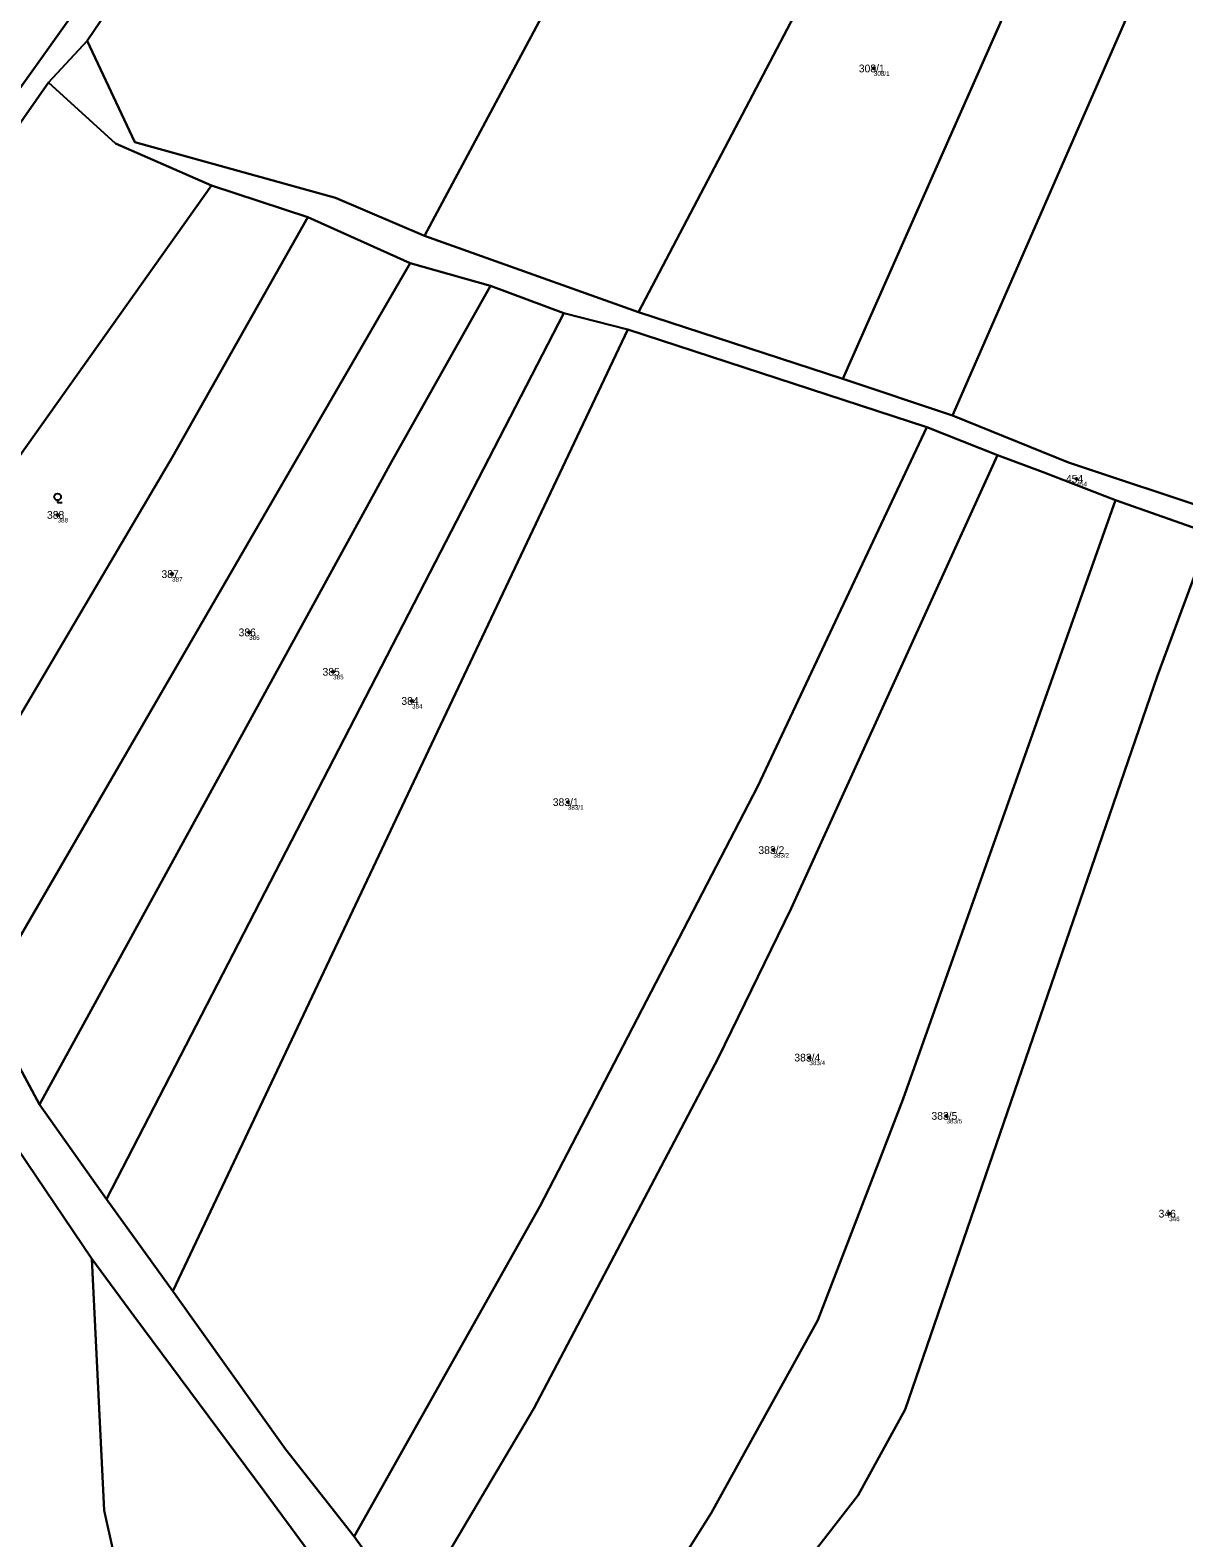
# Model space of a CAD drawing. Extents: x -700238 to -698499, y -1070626 to -1068006.
# Drawn here: x -699749.9 to -699496.8, y -1070051.8 to -1069721.2 of the extents above; entities that cross this region are included whole.
import ezdxf

# ---------------------------------------------------------------- set-up
doc = ezdxf.new("R2010")
doc.units = 0
for name, color, linetype in [('Definiční body', 7, 'Continuous'), ('Hranice parcel', 7, 'Continuous'), ('Parcelní čísla', 7, 'Continuous'), ('Polygon parcely', 7, 'Continuous'), ('Značky kultur', 7, 'Continuous')]:
    doc.layers.add(name, color=color, linetype=linetype)

msp = doc.modelspace()

# ---------------------------------------------------------------- linework, layer by layer
at = {"layer": 'Definiční body'}
for centre in [(-699564.79, -1069729.56994), (-699520.33, -1069819.56994), (-699743.85, -1069827.47994), (-699718.73, -1069840.45994), (-699701.82, -1069853.23994), (-699683.4, -1069861.88994), (-699666.11, -1069868.27994), (-699631.92, -1069890.46994), (-699586.82, -1069900.98994), (-699578.93, -1069946.48994), (-699548.86, -1069959.26994), (-699500, -1069980.70994)]:
    msp.add_circle(centre, 0.25, dxfattribs=at)
at = {"layer": 'Hranice parcel'}
for p, q in [((-699616.44, -1069783.03), (-699549.64, -1069655.89)), ((-699571.62, -1069797.63), (-699516.58, -1069673.38)), ((-699737.33, -1069723.55), (-699745.82, -1069732.62)), ((-699745.82, -1069732.62), (-699776.22, -1069775.97)), ((-699710.07, -1069755.22), (-699786.04, -1069862.19)), ((-699688.94, -1069762.18), (-699710.07, -1069755.22)), ((-699688.94, -1069762.18), (-699666.52, -1069772.25)), ((-699616.44, -1069783.03), (-699663.38, -1069766.26)), ((-699666.52, -1069772.25), (-699760.19, -1069933.83)), ((-699666.52, -1069772.25), (-699648.85, -1069777.23)), ((-699648.85, -1069777.23), (-699632.79, -1069783.26)), ((-699571.62, -1069797.63), (-699616.44, -1069783.03)), ((-699632.79, -1069783.26), (-699618.77, -1069786.84)), ((-699618.77, -1069786.84), (-699553.13, -1069808.24)), ((-699547.54, -1069805.7), (-699571.62, -1069797.63)), ((-699553.13, -1069808.24), (-699537.64, -1069814.41)), ((-699511.76, -1069824.23), (-699491.01, -1069831.53)), ((-699747.8, -1069956.79), (-699760.19, -1069933.83)), ((-699733.13, -1069977.54), (-699747.8, -1069956.79)), ((-699718.55, -1069997.74), (-699733.13, -1069977.54)), ((-699666.31, -1070068.88), (-699678.79, -1070051.48))]:
    msp.add_line(p, q, dxfattribs=at)
for points in [[(-699663.38, -1069766.26), (-699588.64, -1069626.6), (-699502.63, -1069463.58)], [(-699410.28, -1069497.79), (-699441.48, -1069563.72), (-699499.48, -1069695.89), (-699547.54, -1069805.7)], [(-699737.33, -1069723.55), (-699717.02, -1069693.47), (-699659.11, -1069627.7), (-699618.38, -1069587.63), (-699595.53, -1069569.04), (-699577.69, -1069541.99)], [(-699807.41, -1069785.71), (-699794.66, -1069783.16), (-699779.48, -1069772.23), (-699717.6, -1069685.48), (-699696.09, -1069660.07), (-699677.27, -1069640.4)], [(-699663.38, -1069766.26), (-699682.85, -1069757.92), (-699726.9, -1069745.77), (-699737.33, -1069723.55)], [(-699710.07, -1069755.22), (-699731.13, -1069746.06), (-699745.82, -1069732.62)], [(-699772.32, -1069905.7), (-699718.65, -1069814.76), (-699688.94, -1069762.18)], [(-699648.85, -1069777.23), (-699670.62, -1069815.86), (-699747.8, -1069956.79)], [(-699632.79, -1069783.26), (-699678.65, -1069872.05), (-699733.13, -1069977.54)], [(-699618.77, -1069786.84), (-699666.98, -1069888.75), (-699718.55, -1069997.74)], [(-699489.13, -1069826.97), (-699522.09, -1069816), (-699547.54, -1069805.7)], [(-699678.79, -1070051.48), (-699638.09, -1069979.15), (-699590.2, -1069886.97), (-699553.13, -1069808.24)], [(-699666.31, -1070068.88), (-699639.37, -1070023.43), (-699598.96, -1069946.58), (-699582.95, -1069913.77), (-699537.64, -1069814.41)], [(-699537.64, -1069814.41), (-699527.68, -1069818.13), (-699511.76, -1069824.23)], [(-699638.4, -1070106.69), (-699600.44, -1070046.39), (-699577.04, -1070004.06), (-699558.35, -1069955.5), (-699511.76, -1069824.23)], [(-699491.01, -1069831.53), (-699502.67, -1069862.92), (-699557.9, -1070023.63), (-699568.2, -1070042.42), (-699591.03, -1070071.83), (-699598.11, -1070087.48), (-699605.82, -1070099.55), (-699627.96, -1070121.02)], [(-699773.88, -1069925.87), (-699754.67, -1069963.44), (-699736.31, -1069990.62)], [(-699719.44, -1070141.14), (-699723.72, -1070090.01), (-699733.66, -1070045.81), (-699736.31, -1069990.62)], [(-699736.31, -1069990.62), (-699727.1, -1070003.14), (-699698.54, -1070041.6), (-699662.16, -1070090.9)], [(-699678.79, -1070051.48), (-699693.87, -1070032.39), (-699718.55, -1069997.74)]]:
    msp.add_lwpolyline(points, dxfattribs=at)
at = {"layer": 'Polygon parcely'}
for points in [[(-699588.64, -1069626.6), (-699502.63, -1069463.58), (-699532.43, -1069462.36), (-699542.13, -1069479.46), (-699556.41, -1069509.75), (-699574.72, -1069544.15), (-699577.69, -1069541.99), (-699595.53, -1069569.04), (-699618.38, -1069587.63), (-699659.11, -1069627.7), (-699717.02, -1069693.47), (-699737.33, -1069723.55), (-699726.9, -1069745.77), (-699682.85, -1069757.92), (-699663.38, -1069766.26)], [(-699549.64, -1069655.89), (-699502.55, -1069565.81), (-699455.2, -1069475.22), (-699473.03, -1069469.4), (-699502.63, -1069463.58), (-699588.64, -1069626.6), (-699663.38, -1069766.26), (-699616.44, -1069783.03)], [(-699432.05, -1069485.06), (-699452.42, -1069528.96), (-699490.02, -1069614.95), (-699516.58, -1069673.38), (-699571.62, -1069797.63), (-699547.54, -1069805.7), (-699499.48, -1069695.89), (-699441.48, -1069563.72), (-699410.28, -1069497.79), (-699430.38, -1069485.94)], [(-699441.48, -1069563.72), (-699499.48, -1069695.89), (-699547.54, -1069805.7), (-699522.09, -1069816), (-699489.13, -1069826.97), (-699429.43, -1069642.62), (-699387.77, -1069511.65), (-699407.42, -1069499.79), (-699410.28, -1069497.79)], [(-699794.66, -1069783.16), (-699779.48, -1069772.23), (-699717.6, -1069685.48), (-699696.09, -1069660.07), (-699677.27, -1069640.4), (-699685.96, -1069634.32), (-699687.82, -1069636.88), (-699698.97, -1069628.88), (-699715.89, -1069617.34), (-699724.79, -1069614.07), (-699727.16, -1069611.21), (-699737.97, -1069630.27), (-699758.73, -1069669.77), (-699796.03, -1069732.47), (-699807.3, -1069760.27), (-699807.41, -1069785.71)], [(-699516.58, -1069673.38), (-699549.64, -1069655.89), (-699616.44, -1069783.03), (-699571.62, -1069797.63)], [(-699745.82, -1069732.62), (-699776.22, -1069775.97), (-699788.87, -1069798.41), (-699791.36, -1069813.75), (-699786.04, -1069862.19), (-699710.07, -1069755.22), (-699731.13, -1069746.06)], [(-699718.65, -1069814.76), (-699688.94, -1069762.18), (-699710.07, -1069755.22), (-699786.04, -1069862.19), (-699772.32, -1069905.7)], [(-699772.32, -1069905.7), (-699760.19, -1069933.83), (-699666.52, -1069772.25), (-699688.94, -1069762.18), (-699718.65, -1069814.76)], [(-699666.52, -1069772.25), (-699760.19, -1069933.83), (-699747.8, -1069956.79), (-699670.62, -1069815.86), (-699648.85, -1069777.23)], [(-699648.85, -1069777.23), (-699670.62, -1069815.86), (-699747.8, -1069956.79), (-699733.13, -1069977.54), (-699678.65, -1069872.05), (-699632.79, -1069783.26)], [(-699678.65, -1069872.05), (-699733.13, -1069977.54), (-699718.55, -1069997.74), (-699666.98, -1069888.75), (-699618.77, -1069786.84), (-699632.79, -1069783.26)], [(-699638.09, -1069979.15), (-699590.2, -1069886.97), (-699553.13, -1069808.24), (-699618.77, -1069786.84), (-699666.98, -1069888.75), (-699718.55, -1069997.74), (-699693.87, -1070032.39), (-699678.79, -1070051.48)], [(-699639.37, -1070023.43), (-699598.96, -1069946.58), (-699582.95, -1069913.77), (-699537.64, -1069814.41), (-699553.13, -1069808.24), (-699590.2, -1069886.97), (-699638.09, -1069979.15), (-699678.79, -1070051.48), (-699666.31, -1070068.88)], [(-699511.76, -1069824.23), (-699527.68, -1069818.13), (-699537.64, -1069814.41), (-699582.95, -1069913.77), (-699598.96, -1069946.58), (-699639.37, -1070023.43), (-699666.31, -1070068.88), (-699659.02, -1070078.07), (-699638.4, -1070106.69), (-699600.44, -1070046.39), (-699577.04, -1070004.06), (-699558.35, -1069955.5)], [(-699627.96, -1070121.02), (-699605.82, -1070099.55), (-699598.11, -1070087.48), (-699591.03, -1070071.83), (-699568.2, -1070042.42), (-699557.9, -1070023.63), (-699502.67, -1069862.92), (-699491.01, -1069831.53), (-699511.76, -1069824.23), (-699558.35, -1069955.5), (-699577.04, -1070004.06), (-699600.44, -1070046.39), (-699638.4, -1070106.69)], [(-699627.96, -1070121.02), (-699583.6, -1070174.87), (-699568.26, -1070192.92), (-699548.5, -1070215.51), (-699529.48, -1070237.61), (-699518.68, -1070249.64), (-699463.77, -1070072.37), (-699431.42, -1069967.33), (-699399.24, -1069862.86), (-699491.01, -1069831.53), (-699502.67, -1069862.92), (-699557.9, -1070023.63), (-699568.2, -1070042.42), (-699591.03, -1070071.83), (-699598.11, -1070087.48), (-699605.82, -1070099.55)], [(-699660.76, -1070101.89), (-699662.16, -1070090.9), (-699698.54, -1070041.6), (-699727.1, -1070003.14), (-699736.31, -1069990.62), (-699733.66, -1070045.81), (-699723.72, -1070090.01), (-699719.44, -1070141.14), (-699692.3, -1070126.13), (-699678.56, -1070118.21), (-699667.65, -1070125.9)]]:
    msp.add_lwpolyline(points, close=True, dxfattribs=at)
for points in [[(-699717.6, -1069685.48), (-699779.48, -1069772.23), (-699794.66, -1069783.16), (-699807.41, -1069785.71), (-699809.76, -1069785.77), (-699808.65, -1069790.69), (-699792.92, -1069786.04), (-699789.4, -1069784.22), (-699776.22, -1069775.97), (-699745.82, -1069732.62), (-699737.33, -1069723.55), (-699717.02, -1069693.47)], [(-699666.31, -1070068.88), (-699678.79, -1070051.48), (-699693.87, -1070032.39), (-699718.55, -1069997.74), (-699733.13, -1069977.54), (-699747.8, -1069956.79), (-699760.19, -1069933.83), (-699772.32, -1069905.7), (-699786.04, -1069862.19), (-699789.84, -1069849.05), (-699797.44, -1069825.52), (-699807.14, -1069798.04), (-699808.65, -1069790.69), (-699809.76, -1069785.77), (-699810.32, -1069782.64), (-699811.1, -1069770), (-699809.25, -1069756.98), (-699803.18, -1069743.13), (-699792.05, -1069721.6), (-699779, -1069695.71)], [(-699489.13, -1069826.97), (-699522.09, -1069816), (-699547.54, -1069805.7), (-699571.62, -1069797.63), (-699616.44, -1069783.03), (-699663.38, -1069766.26), (-699682.85, -1069757.92), (-699726.9, -1069745.77), (-699737.33, -1069723.55), (-699745.82, -1069732.62), (-699731.13, -1069746.06), (-699710.07, -1069755.22), (-699688.94, -1069762.18), (-699666.52, -1069772.25), (-699648.85, -1069777.23), (-699632.79, -1069783.26), (-699618.77, -1069786.84), (-699553.13, -1069808.24), (-699537.64, -1069814.41), (-699527.68, -1069818.13), (-699511.76, -1069824.23), (-699491.01, -1069831.53)], [(-699820.65, -1069756.64), (-699822.8, -1069770.73), (-699819.03, -1069786.16), (-699815.5, -1069803.39), (-699809.91, -1069821.04), (-699795.87, -1069862.82), (-699793.62, -1069871.36), (-699786.24, -1069895), (-699780.65, -1069910.87), (-699776.82, -1069919.37), (-699773.88, -1069925.87), (-699754.67, -1069963.44), (-699736.31, -1069990.62), (-699727.1, -1070003.14), (-699698.54, -1070041.6), (-699662.16, -1070090.9)], [(-699723.72, -1070090.01), (-699733.66, -1070045.81), (-699736.31, -1069990.62), (-699754.67, -1069963.44), (-699773.88, -1069925.87), (-699775.47, -1069950.06), (-699776.09, -1069961.97), (-699774.25, -1069975.35), (-699760.75, -1070039.69), (-699757.63, -1070065.88)]]:
    msp.add_lwpolyline(points, dxfattribs=at)
at = {"layer": 'Značky kultur'}
for p, q in [((-699743.85, -1069824.282), (-699743.85, -1069824.78)), ((-699743.85, -1069824.78), (-699742.849, -1069824.78))]:
    msp.add_line(p, q, dxfattribs=at)
msp.add_circle((-699743.84929, -1069823.5309), 0.75, dxfattribs=at)

# ---------------------------------------------------------------- texts
at = {"layer": 'Definiční body'}
for s, p in [('308/1', (-699564.79, -1069731.226)), ('454', (-699520.33, -1069821.226)), ('388', (-699743.85, -1069829.136)), ('387', (-699718.73, -1069842.116)), ('386', (-699701.82, -1069854.896)), ('385', (-699683.4, -1069863.546)), ('384', (-699666.11, -1069869.936)), ('383/1', (-699631.92, -1069892.126)), ('383/2', (-699586.82, -1069902.646)), ('383/4', (-699578.93, -1069948.146)), ('383/5', (-699548.86, -1069960.926)), ('346', (-699500, -1069982.366))]:
    msp.add_text(s, height=0.999996, dxfattribs=at).set_placement(p)
at = {"layer": 'Parcelní čísla'}
for s, p in [('308/1', (-699568.088, -1069730.42)), ('454', (-699522.655, -1069820.42)), ('388', (-699746.175, -1069828.33)), ('387', (-699721.055, -1069841.31)), ('386', (-699704.145, -1069854.09)), ('385', (-699685.725, -1069862.739)), ('384', (-699668.435, -1069869.13)), ('383/1', (-699635.218, -1069891.32)), ('383/2', (-699590.118, -1069901.84)), ('383/4', (-699582.228, -1069947.34)), ('383/5', (-699552.158, -1069960.12)), ('346', (-699502.325, -1069981.56))]:
    msp.add_text(s, height=1.699998, dxfattribs=at).set_placement(p)

doc.saveas('drawing.dxf')
